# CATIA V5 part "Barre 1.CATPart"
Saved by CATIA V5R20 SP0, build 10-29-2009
Part number: Barre 1
Bounding box of the stored display mesh (mm): x 290.113 to 404.638, y -9.883 to 323.648, z 0 to 10
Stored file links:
  C:\Users\Matthieu\Desktop\IFMA\Cours 2A\Thinkmotion\Projet_IAO_714_Matthieu_Perrusset\Barre 1.CATPart
  C:\Users\Matthieu\Desktop\IFMA\Cours 2A\Thinkmotion\Ass_skl_IAO.CATProduct
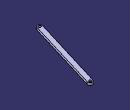
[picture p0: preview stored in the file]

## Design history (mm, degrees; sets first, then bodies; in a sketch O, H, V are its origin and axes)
AxisSystem1: origin (0, 0, 0), X (1, 0, 0), Y (0, 1, 0), Z (0, 0, 1)
Set1
  Plane1 "Plan_Ref": linked copy from another document
  Line1 "Barre_1": linked copy from another document
  Line2 "Axe_Pivot_G": linked copy from another document
  Line3 "Axe_Pivot_b1b9": linked copy from another document
Body1 (main body)
  Sketch1 on Plane1, origin (0, 0, 0), H (1, 0, 0), V (0, 1, 0)
    line L1 (309.5734, -2.8896) -> (404.2443, 310.7588)
    arc A1 centre (394.6709, 313.6485) radius 10 from (404.2443, 310.7588) to (384.6897, 314.2607) ccw
    point P3 (394.6709, 313.6485)
    line L2 (384.6897, 314.2607) -> (291.3469, 5.0123)
    arc A2 centre (300, 0) radius 10 from (291.3469, 5.0123) to (309.5734, -2.8896) ccw
    point P6 (300, 0)
    reference projected point E1 (300, 0) from Line2
    reference projected point E2 (394.6709, 313.6485) from Line3
    reference projected line E3 (394.6709, 313.6485) -> (300, 0) from Line1
    reference projected line E4 (394.6709, 313.6485) -> (300, 0) from Line1
    reference projected line E5 (394.6709, 313.6485) -> (300, 0) from Line1
    reference projected point E6 (394.6709, 313.6485) from Line3
    reference projected point E7 (300, 0) from Line2
    circle A3 centre (394.6709, 313.6485) radius 5
    circle A4 centre (300, 0) radius 5
    distance E5 L1 = 10
    distance E6 A1 = 10
    distance E7 A2 = 10
    radius A3 = 5
    radius A4 = 5
    coincidence: E1 P6, E2 P3
    parallelism: E3 L1, L2 E4
  Pad1: profile Sketch1, direction (0, 0, 1), length 10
